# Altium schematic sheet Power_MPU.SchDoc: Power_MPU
size A3; CompanyName: STMicroelectronics; DocumentNumber: MB1263; Revision: C-04; SheetNumber: 4; SheetTotal: 11; Project: STM32MP157-EVAL
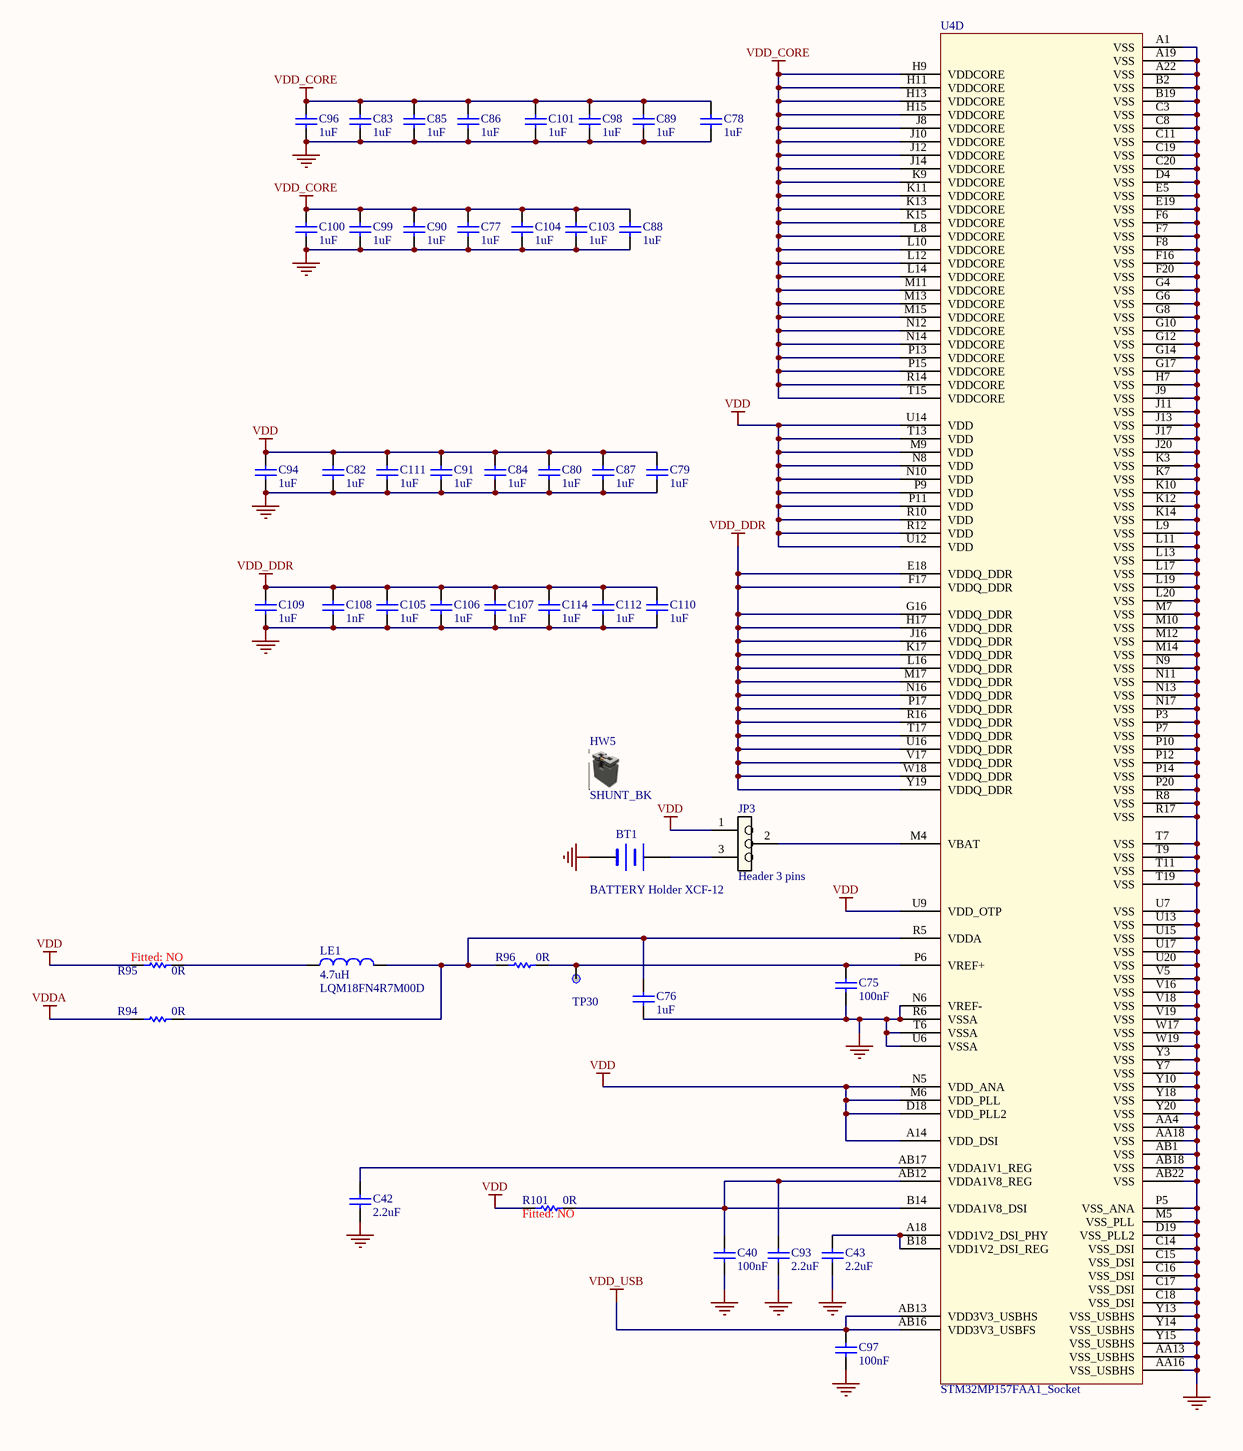
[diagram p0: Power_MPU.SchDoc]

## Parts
BT1  BATTERY Holder XCF-12  [BAT_CHINA_XCF-12_SMD_2P]
C40  100nF  [C0402]
C42  2.2uF  [C0402]
C43  2.2uF  [C0402]
C75  100nF  [C0402]
C76  1uF  [C0603]
C77  1uF  [C0402]
C78  1uF  [C0402]
C79  1uF  [C0402]
C80  1uF  [C0402]
C82  1uF  [C0402]
C83  1uF  [C0402]
C84  1uF  [C0402]
C85  1uF  [C0402]
C86  1uF  [C0402]
C87  1uF  [C0402]
C88  1uF  [C0402]
C89  1uF  [C0402]
C90  1uF  [C0402]
C91  1uF  [C0402]
C93  2.2uF  [C0402]
C94  1uF  [C0402]
C96  1uF  [C0402]
C97  100nF  [C0402]
C98  1uF  [C0402]
C99  1uF  [C0402]
C100  1uF  [C0402]
C101  1uF  [C0402]
C103  1uF  [C0402]
C104  1uF  [C0402]
C105  1uF  [C0402]
C106  1uF  [C0402]
C107  1nF  [C0402]
C108  1nF  [C0402]
C109  1uF  [C0402]
C110  1uF  [C0402]
C111  1uF  [C0402]
C112  1uF  [C0402]
C114  1uF  [C0402]
HW5  SHUNT_BK  (mechanical)
JP3  Header 3 pins  [CON_SAMTEC_TSW-103-07-F-S]
LE1  Manuf_Part_1: LQM18FN4R7M00D  [L0603]  (hidden comment: 4.7uH)
R94  0R  [R0402]
R95  0R  Fitted: NO  [R0402]
R96  0R  [R0402]
R101  0R  Fitted: NO  [R0402]
TP30  TP  [TP_SMD_1MM]  (value not drawn)  (no BOM)
U4  STM32MP157FAA1_Socket  [ICC_LFBGA448_18X18_STM32MP157BAA3_P080__SOCKET_IE_CS1627194MF]  (part D of 5)

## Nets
GND: BT1.2(-) C40.1 C42.1 C43.1 C75.1 C76.1 C77.1 C78.1 C79.1 C80.1 C82.1 C83.1 C84.1 C85.1 C86.1 C87.1 C88.1 C89.1 C90.1 C91.1 C93.1 C94.1 C96.1 C97.1 C98.1 C99.1 C100.1 C101.1 C103.1 C104.1 C105.1 C106.1 C107.1 C108.1 C109.1 C110.1 C111.1 C112.1 C114.1 U4.A1(VSS) U4.A19(VSS) U4.A22(VSS) U4.AA4(VSS) U4.AA13(VSS_USBHS) U4.AA16(VSS_USBHS) U4.AA18(VSS) U4.AB1(VSS) U4.AB18(VSS) U4.AB22(VSS) U4.B2(VSS) U4.B19(VSS) U4.C3(VSS) U4.C8(VSS) U4.C11(VSS) U4.C14(VSS_DSI) U4.C15(VSS_DSI) U4.C16(VSS_DSI) U4.C17(VSS_DSI) U4.C18(VSS_DSI) U4.C19(VSS) U4.C20(VSS) U4.D4(VSS) U4.D19(VSS_PLL2) U4.E5(VSS) U4.E19(VSS) U4.F6(VSS) U4.F7(VSS) U4.F8(VSS) U4.F16(VSS) U4.F20(VSS) U4.G4(VSS) U4.G6(VSS) U4.G8(VSS) U4.G10(VSS) U4.G12(VSS) U4.G14(VSS) U4.G17(VSS) U4.H7(VSS) U4.J9(VSS) U4.J11(VSS) U4.J13(VSS) U4.J17(VSS) U4.J20(VSS) U4.K3(VSS) U4.K7(VSS) U4.K10(VSS) U4.K12(VSS) U4.K14(VSS) U4.L9(VSS) U4.L11(VSS) U4.L13(VSS) U4.L17(VSS) U4.L19(VSS) U4.L20(VSS) U4.M5(VSS_PLL) U4.M7(VSS) U4.M10(VSS) U4.M12(VSS) U4.M14(VSS) U4.N6(VREF-) U4.N9(VSS) U4.N11(VSS) U4.N13(VSS) U4.N17(VSS) U4.P3(VSS) U4.P5(VSS_ANA) U4.P7(VSS) U4.P10(VSS) U4.P12(VSS) U4.P14(VSS) U4.P20(VSS) U4.R6(VSSA) U4.R8(VSS) U4.R17(VSS) U4.T6(VSSA) U4.T7(VSS) U4.T9(VSS) U4.T11(VSS) U4.T19(VSS) U4.U6(VSSA) U4.U7(VSS) U4.U13(VSS) U4.U15(VSS) U4.U17(VSS) U4.U20(VSS) U4.V5(VSS) U4.V16(VSS) U4.V18(VSS) U4.V19(VSS) U4.W17(VSS) U4.W19(VSS) U4.Y3(VSS) U4.Y7(VSS) U4.Y10(VSS) U4.Y13(VSS_USBHS) U4.Y14(VSS_USBHS) U4.Y15(VSS_USBHS) U4.Y18(VSS) U4.Y20(VSS)
VDD: C79.2 C80.2 C82.2 C84.2 C87.2 C91.2 C94.2 C111.2 JP3.1 R95.1 R101.1 U4.A14(VDD_DSI) U4.D18(VDD_PLL2) U4.M6(VDD_PLL) U4.M9(VDD) U4.N5(VDD_ANA) U4.N8(VDD) U4.N10(VDD) U4.P9(VDD) U4.P11(VDD) U4.R10(VDD) U4.R12(VDD) U4.T13(VDD) U4.U9(VDD_OTP) U4.U12(VDD) U4.U14(VDD)
VDD_CORE: C77.2 C78.2 C83.2 C85.2 C86.2 C88.2 C89.2 C90.2 C96.2 C98.2 C99.2 C100.2 C101.2 C103.2 C104.2 U4.H9(VDDCORE) U4.H11(VDDCORE) U4.H13(VDDCORE) U4.H15(VDDCORE) U4.J8(VDDCORE) U4.J10(VDDCORE) U4.J12(VDDCORE) U4.J14(VDDCORE) U4.K9(VDDCORE) U4.K11(VDDCORE) U4.K13(VDDCORE) U4.K15(VDDCORE) U4.L8(VDDCORE) U4.L10(VDDCORE) U4.L12(VDDCORE) U4.L14(VDDCORE) U4.M11(VDDCORE) U4.M13(VDDCORE) U4.M15(VDDCORE) U4.N12(VDDCORE) U4.N14(VDDCORE) U4.P13(VDDCORE) U4.P15(VDDCORE) U4.R14(VDDCORE) U4.T15(VDDCORE)
VDD_DDR: C105.2 C106.2 C107.2 C108.2 C109.2 C110.2 C112.2 C114.2 U4.E18(VDDQ_DDR) U4.F17(VDDQ_DDR) U4.G16(VDDQ_DDR) U4.H17(VDDQ_DDR) U4.J16(VDDQ_DDR) U4.K17(VDDQ_DDR) U4.L16(VDDQ_DDR) U4.M17(VDDQ_DDR) U4.N16(VDDQ_DDR) U4.P17(VDDQ_DDR) U4.R16(VDDQ_DDR) U4.T17(VDDQ_DDR) U4.U16(VDDQ_DDR) U4.V17(VDDQ_DDR) U4.W18(VDDQ_DDR) U4.Y19(VDDQ_DDR)
VDD_USB: C97.2 U4.AB13(VDD3V3_USBHS) U4.AB16(VDD3V3_USBFS)
VDDA: R94.1
NetBT1_1: BT1.1(+) JP3.3
NetC40_2: C40.2 C93.2 R101.2 U4.AB12(VDDA1V8_REG) U4.B14(VDDA1V8_DSI)
NetC42_2: C42.2 U4.AB17(VDDA1V1_REG)
NetC43_2: C43.2 U4.A18(VDD1V2_DSI_PHY) U4.B18(VDD1V2_DSI_REG)
NetC75_2: C75.2 R96.2 TP30.1 U4.P6(VREF+)
NetC76_2: C76.2 LE1.2 R94.2 R96.1 U4.R5(VDDA)
NetJP3_2: JP3.2 U4.M4(VBAT)
NetLE1_1: LE1.1 R95.2

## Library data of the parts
BT1 = BATTERY Holder XCF-12: Battery  holder xcfbattery XCF-12; Fitted: YES; Ordered_By: Subcon
C40 C75 C97 = Cap_100nF_X7R_10%_0402: Capacitor,100nF,16V,X7R,10%,0402,YAGEO; Manuf_Part_1: CC0402KRX7R7BB104; Fitted: YES; Ordered_By: Subcon
C42 C43 C93 = Cap_2.2uF_X5R_10%_6V3_0402: Capacitor,MLCC,2.2uF,6V3,X5R,10%,0402,T=0.5; Manuf_Part_1: GRM155R60J225KE95D; Manuf_1: MURATA; Fitted: YES; Ordered_By: Subcon
C76 = Cap_1uF_X5R_10%_0603: Capacitor,1uF,16V,X5R,10%,0603,YAGEO; Manuf_Part_1: CC0603KRX5R7BB105; Fitted: YES; Ordered_By: Subcon
C77-C80 C82-C91 C94 C96 C98-C101 C103-C106 C109-C112 C114 = Cap_1uF_X5R_10%_6V3_0402: Capacitor MLCC 1µF 10% 6,3V 0,4uF@3,3V X5R 0402 MURATA; Manuf_Part_1: GRM155R61E105KA12; Fitted: YES; Ordered_By: Subcon
C107 C108 = Cap_1nF_X7R_10%_0402: Capacitor,1nF,16V,X7R,10%,0402,YAGEO; Manuf_Part_1: CC0402KRX7R7BB102; Order_Code: 1816754; Fitted: YES; Ordered_By: Subcon
HW5 = Shunt 2.54mm: SHUNT 2.54mm BLACK; Manuf_1: SAMTEC; Manuf_Part_1: SNT-100-BK-G; Fitted: YES; Ordered_By: Subcon
JP3 = Header 3: Header, 3-Pin; Manuf_1: Samtec; Manuf_Part_1: TSW-103-07-F-S; Fitted: YES; Ordered_By: Subcon
LE1 = IND_4.7uH 600mohm_80mA_0603: IND 4.7µH 20% 80mA 600mhom 0603; Manuf_1: MURATA; Ordered_By: Subcon; Fitted: YES
R94 R96 = Res_0_5%_0402: Resistor,0R,0402,5%,YAGEO; Manuf_Part_1: RC0402JR-070RL; Order_Code: 2363467; Fitted: YES; Ordered_By: Subcon
R95 R101 = Res_0_5%_0402: Resistor,0R,0402,5%,YAGEO; Manuf_Part_1: RC0402JR-070RL; Order_Code: 2363467; Ordered_By: Subcon
TP30 = TP 1mm: Test Point; Fitted: YES
U4 = STM32MP157FAA1_Socket: MPU LFBGA18x18 with crypto-Increased Frequency; Manuf_1: ST; Fitted: YES; Ordered_By: Subcon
